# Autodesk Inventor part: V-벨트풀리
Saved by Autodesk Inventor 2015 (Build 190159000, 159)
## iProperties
Created: 2025-08
Part Number: V-벨트풀리
Material: 일반
Document SubType Name: Modeling
Designer: USER
Density: 1 g/cm^3
Appearance: 기본값
Author: USER
Author: jhkim
Creation Date: 2025-08-05
Sending System: Autodesk Inventor 2026
Preprocessor: ST-DEVELOPER v20.1
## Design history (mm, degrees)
node "V-벨트풀리1"
node "솔리드1"
node "기준1"
